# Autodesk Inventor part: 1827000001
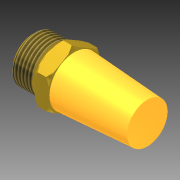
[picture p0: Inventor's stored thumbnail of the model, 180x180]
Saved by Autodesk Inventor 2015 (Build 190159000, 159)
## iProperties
Created: 2013-02
Part Number: 1827000001
Material: Generic
Document SubType Name: Modeling
Designer: Marci
Density: 1 g/cm^3
Appearance: Glossy - Gold
Translation Standard: STEP AP214IS
FileName: 1827000001
PreProcessor: PRO/ENGINEER BY PARAMETRIC TECHNOLOGY CORPORATION, 2006020
PostProcessor: Build: 160, Release: 2012 RTM - Date: Tue 03/01/2011
Sent Units: millimeter
Uncertainty: 0.004083215476456
Author: Marci
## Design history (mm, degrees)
node "18270000011"
thread "Thread1" dims "d0" = 10, "d1" = 0
node "1827000001"
node "Base1"
